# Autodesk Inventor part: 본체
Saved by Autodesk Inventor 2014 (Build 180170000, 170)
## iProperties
Created: 2026-08
Part Number: 본체
Material: 알루미늄 6061
Document SubType Name: Modeling
Designer: dg
Density: 2.71 g/cm^3
Appearance: 알루미늄 - 평지
Author: jhkim
Creation Date: 2026-07-31
Sending System: Autodesk Inventor 2027
Preprocessor: ST-DEVELOPER v20.1
Author: dg
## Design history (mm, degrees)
node "본체1"
node "솔리드1"
node "기준1"
